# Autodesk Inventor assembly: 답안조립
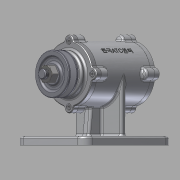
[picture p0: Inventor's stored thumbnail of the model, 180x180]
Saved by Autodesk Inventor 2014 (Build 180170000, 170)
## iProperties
Created: 2015-12
Part Number: 답안조립
Document SubType Name: Assembly
Designer: L-10
Author: L-10
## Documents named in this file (11)
- C:\Users\L-10\Desktop\451208V1037\답안조립품.iam
- C:\Users\L-10\Desktop\451208V1037\본체.ipt
- C:\Users\L-10\Desktop\451208V1037\커버.ipt
- C:\Users\L-10\Desktop\451208V1037\커버2.ipt
- C:\Users\L-10\Desktop\451208V1037\볼트 M4 x 12.ipt
- C:\Users\L-10\Desktop\451208V1037\베어링 6204.ipt
- C:\Users\L-10\Desktop\451208V1037\축.ipt
- C:\Users\L-10\Desktop\451208V1037\V-벨트풀리.ipt
- C:\Users\L-10\Desktop\451208V1037\키(4 x 4 x 12).ipt
- C:\Users\L-10\Desktop\451208V1037\오일실.ipt
- C:\Users\L-10\Desktop\451208V1037\너트 M12x1.25.ipt
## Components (6 placed, 5 different names)
1. KS B 2023 6204 - 20 x 47 x 14:1
2. KS B 2023 6204 - 20 x 47 x 14:2
3. V-벨트풀리:1
4. KS B 1311 (I) 4 x 4 x 12:1
5. KS B 2804 D D - 20 32 8:1
6. KS B 1012 클래스 1 일반 - 미터 M12x1.25:1
